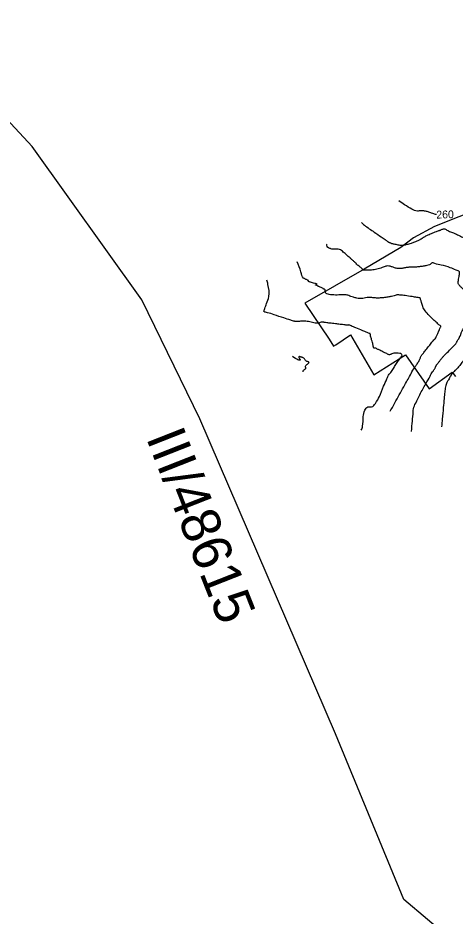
# Model space of a CAD drawing. Extents: x -478645 to -472650, y -1118147 to -1113892.
# Drawn here: x -476588 to -476364.6, y -1115811.7 to -1115352.3 of the extents above; entities that cross this region are included whole.
import ezdxf

# ---------------------------------------------------------------- set-up
doc = ezdxf.new("R2010")
doc.units = 0
for name, color, linetype in [('ObPÚ', 7, 'Continuous'), ('silnice', 7, 'Continuous'), ('Vrstevnice_hlavni', 7, 'Continuous'), ('Vrstevnice_popis', 7, 'Continuous'), ('Vrstevnice_vedlejsi', 7, 'Continuous')]:
    doc.layers.add(name, color=color, linetype=linetype)

msp = doc.modelspace()

# ---------------------------------------------------------------- linework, layer by layer
at = {"layer": 'ObPÚ'}
msp.add_lwpolyline([(-476350.14, -1115449), (-476375.02, -1115459.02), (-476385.85, -1115464.8), (-476392.23, -1115469.66), (-476411.03, -1115480.79), (-476441.42, -1115498.26), (-476428.9, -1115516.62), (-476426.71, -1115520.24), (-476425.46, -1115519.42), (-476418.11, -1115514.37), (-476406.06, -1115534.8), (-476390, -1115524.57), (-476377.76, -1115542), (-476366.06, -1115533.41), (-476364.38, -1115535.62)], dxfattribs=at)
at = {"layer": 'silnice'}
msp.add_lwpolyline([(-476162.8, -1116322.7), (-476200.543, -1116268.153), (-476239.965, -1116179.199), (-476260.934, -1116109.546), (-476288.613, -1116007.164), (-476289.451, -1115970.24), (-476274.354, -1115930.798), (-476261.922, -1115907.288), (-476366.595, -1115823.727), (-476390.845, -1115803.24), (-476425.665, -1115718.481), (-476494.983, -1115557.356), (-476524.795, -1115496.42), (-476580.823, -1115418.032), (-476641.911, -1115352.297)], dxfattribs=at)
at = {"layer": 'Vrstevnice_hlavni'}
for points in [[(-476374.118, -1115452.894), (-476374.632, -1115452.768), (-476375.379, -1115452.515), (-476376.616, -1115452.074), (-476378.342, -1115451.442), (-476380.123, -1115451.064), (-476381.96, -1115450.937), (-476383.851, -1115451.062), (-476386.654, -1115450.049), (-476390.368, -1115447.898), (-476393.306, -1115445.807)], [(-476442.249, -1115533.315), (-476442.258, -1115533.223), (-476442.035, -1115532.45), (-476441.322, -1115531.991), (-476440.926, -1115531.554), (-476440.848, -1115531.138), (-476441.086, -1115530.744), (-476441.04, -1115530.317), (-476440.708, -1115529.858), (-476440.091, -1115529.366), (-476439.638, -1115528.987), (-476439.349, -1115528.72), (-476439.224, -1115528.565), (-476439.347, -1115528.386), (-476439.718, -1115528.183), (-476440.335, -1115527.956), (-476440.852, -1115527.632), (-476441.268, -1115527.211), (-476441.584, -1115526.693), (-476441.969, -1115526.298), (-476442.426, -1115526.027), (-476442.953, -1115525.878), (-476443.443, -1115525.735), (-476443.895, -1115525.597), (-476444.309, -1115525.465), (-476444.44, -1115525.662), (-476444.286, -1115526.188), (-476443.849, -1115527.043), (-476447.74, -1115525.503)]]:
    msp.add_spline(points, degree=3, dxfattribs=at)
at = {"layer": 'Vrstevnice_vedlejsi'}
for points in [[(-476412.487, -1115456.977), (-476410.913, -1115458.262), (-476405.882, -1115461.815), (-476402.37, -1115464.29), (-476400.376, -1115465.685), (-476399.9, -1115466), (-476399.472, -1115466.293), (-476399.093, -1115466.564), (-476398.763, -1115466.813), (-476398.4, -1115467.035), (-476398.006, -1115467.232), (-476397.581, -1115467.402), (-476397, -1115467.583), (-476396.264, -1115467.775), (-476395.373, -1115467.977), (-476394.42, -1115468.176), (-476393.405, -1115468.369), (-476392.328, -1115468.558), (-476390.887, -1115468.463), (-476389.082, -1115468.084), (-476386.914, -1115467.422), (-476385.197, -1115466.84), (-476383.932, -1115466.337), (-476383.118, -1115465.915), (-476382.467, -1115465.566), (-476381.978, -1115465.291), (-476381.65, -1115465.088), (-476381.304, -1115464.864), (-476380.937, -1115464.618), (-476380.551, -1115464.349), (-476379.903, -1115463.998), (-476378.994, -1115463.563), (-476377.824, -1115463.044), (-476376.623, -1115462.523), (-476375.392, -1115462)], [(-476375.392, -1115462), (-476374.129, -1115461.473), (-476373.218, -1115461.118), (-476372.659, -1115460.933), (-476372.45, -1115460.919), (-476372.087, -1115460.802), (-476371.568, -1115460.58), (-476370.895, -1115460.255), (-476370.204, -1115460.181), (-476369.496, -1115460.36), (-476368.77, -1115460.791), (-476367.914, -1115461.219), (-476366.926, -1115461.642), (-476365.807, -1115462.062), (-476364.304, -1115462.716), (-476362.417, -1115463.605), (-476360.145, -1115464.728), (-476357.641, -1115465.438), (-476354.904, -1115465.734), (-476351.935, -1115465.618), (-476349.849, -1115465.502), (-476348.647, -1115465.387), (-476348.329, -1115465.272), (-476347.968, -1115465.34), (-476347.565, -1115465.59), (-476347.119, -1115466.023), (-476346.516, -1115466.573), (-476345.755, -1115467.242), (-476344.837, -1115468.03), (-476344.033, -1115469.141), (-476343.343, -1115470.576), (-476342.768, -1115472.335), (-476342.342, -1115473.633), (-476342.065, -1115474.468), (-476341.938, -1115474.841), (-476341.36, -1115475.721), (-476340.333, -1115477.106), (-476338.856, -1115478.997), (-476337.825, -1115480.446), (-476337.242, -1115481.454), (-476337.106, -1115482.02), (-476336.708, -1115482.699), (-476336.047, -1115483.489), (-476335.123, -1115484.392), (-476334.613, -1115485.234), (-476334.515, -1115486.014), (-476334.83, -1115486.732), (-476335.165, -1115487.505), (-476335.519, -1115488.332), (-476335.893, -1115489.212), (-476336.181, -1115489.954), (-476336.384, -1115490.556), (-476336.5, -1115491.018), (-476336.678, -1115491.638), (-476336.918, -1115492.417), (-476337.22, -1115493.354), (-476337.658, -1115494.21), (-476338.234, -1115494.984), (-476338.946, -1115495.678), (-476339.549, -1115496.226), (-476340.042, -1115496.627), (-476340.425, -1115496.883), (-476340.759, -1115497.34), (-476341.045, -1115497.997), (-476341.282, -1115498.856), (-476341.828, -1115499.854), (-476342.682, -1115500.993), (-476343.846, -1115502.272), (-476344.811, -1115503.411), (-476345.578, -1115504.411), (-476346.146, -1115505.272), (-476346.807, -1115506.216), (-476347.56, -1115507.242), (-476348.405, -1115508.352), (-476349.595, -1115510.321), (-476351.128, -1115513.152), (-476353.005, -1115516.842), (-476354.314, -1115519.344), (-476355.055, -1115520.656), (-476355.227, -1115520.78), (-476355.538, -1115521.104), (-476355.989, -1115521.629), (-476356.58, -1115522.354), (-476357.559, -1115523.662), (-476358.927, -1115525.554), (-476360.684, -1115528.028), (-476362.218, -1115530.038), (-476363.528, -1115531.584), (-476364.614, -1115532.666), (-476365.375, -1115533.438), (-476365.811, -1115533.898), (-476365.922, -1115534.047), (-476366.035, -1115534.195), (-476366.151, -1115534.34), (-476366.269, -1115534.483), (-476366.37, -1115534.607), (-476366.453, -1115534.711)], [(-476390.415, -1115480.123), (-476392.093, -1115480.442), (-476393.773, -1115480.449), (-476395.455, -1115480.141), (-476397.138, -1115479.52), (-476398.521, -1115479.202), (-476399.606, -1115479.187), (-476400.391, -1115479.474), (-476401.353, -1115479.819), (-476402.494, -1115480.221), (-476403.813, -1115480.681), (-476405.189, -1115481.004), (-476406.622, -1115481.191), (-476408.113, -1115481.24), (-476409.287, -1115481.28), (-476410.144, -1115481.31), (-476410.685, -1115481.331), (-476411.093, -1115481.319), (-476411.368, -1115481.273), (-476411.51, -1115481.194), (-476411.664, -1115481.065), (-476411.83, -1115480.886), (-476412.009, -1115480.658), (-476412.452, -1115480.262), (-476413.159, -1115479.699), (-476414.132, -1115478.968), (-476414.756, -1115478.466), (-476415.033, -1115478.195), (-476414.961, -1115478.152), (-476415.298, -1115477.773), (-476416.042, -1115477.057), (-476417.195, -1115476.004), (-476418.233, -1115475.067), (-476419.157, -1115474.246), (-476419.967, -1115473.541), (-476420.822, -1115472.803), (-476421.721, -1115472.032), (-476422.665, -1115471.228), (-476423.717, -1115470.72), (-476424.877, -1115470.508), (-476426.145, -1115470.593), (-476427.196, -1115470.561), (-476428.028, -1115470.413), (-476428.643, -1115470.148), (-476429.106, -1115469.938), (-476429.418, -1115469.785), (-476429.579, -1115469.688), (-476430.087, -1115468.492), (-476430.298, -1115467.927)], [(-476435.156, -1115488.388), (-476435.158, -1115488.388), (-476435.557, -1115488.278), (-476436.352, -1115488.058), (-476437.543, -1115487.729), (-476438.431, -1115487.476), (-476439.016, -1115487.299), (-476439.298, -1115487.198), (-476439.46, -1115487.083), (-476439.502, -1115486.954), (-476439.423, -1115486.81), (-476439.571, -1115486.628), (-476439.947, -1115486.406), (-476440.549, -1115486.147), (-476441.093, -1115485.887), (-476441.577, -1115485.629), (-476442.002, -1115485.371), (-476443.347, -1115482.202), (-476445.27, -1115477.051)], [(-476386.868, -1115563.77), (-476386.404, -1115558.49), (-476385.983, -1115553.73), (-476385.843, -1115552.17), (-476384.718, -1115549.256), (-476382.607, -1115544.988), (-476379.51, -1115539.367), (-476377.347, -1115535.488), (-476376.117, -1115533.352), (-476375.821, -1115532.959), (-476375.527, -1115532.539), (-476375.236, -1115532.091), (-476374.948, -1115531.616), (-476374.711, -1115531.173), (-476374.526, -1115530.763), (-476374.393, -1115530.385), (-476374.22, -1115530.026), (-476374.008, -1115529.686), (-476373.756, -1115529.365), (-476373.437, -1115528.968), (-476373.052, -1115528.496), (-476372.6, -1115527.948), (-476372.158, -1115527.393), (-476371.726, -1115526.831), (-476371.304, -1115526.261), (-476370.255, -1115525.116), (-476368.58, -1115523.398), (-476366.278, -1115521.105), (-476364.681, -1115519.417), (-476363.788, -1115518.333), (-476363.599, -1115517.854), (-476363.38, -1115517.403), (-476363.131, -1115516.981), (-476362.852, -1115516.586), (-476362.624, -1115516.208), (-476362.447, -1115515.848), (-476362.32, -1115515.506), (-476362.183, -1115515.228), (-476362.036, -1115515.015), (-476361.879, -1115514.866), (-476361.743, -1115514.589), (-476361.628, -1115514.182), (-476361.535, -1115513.647), (-476361.302, -1115513.008), (-476360.931, -1115512.265), (-476360.421, -1115511.418), (-476359.844, -1115510.674), (-476359.201, -1115510.032), (-476358.493, -1115509.493), (-476357.886, -1115508.861), (-476357.381, -1115508.138), (-476356.978, -1115507.323), (-476356.457, -1115506.284), (-476355.818, -1115505.02), (-476355.061, -1115503.532), (-476354.274, -1115502.169), (-476353.457, -1115500.932), (-476352.611, -1115499.821), (-476352.458, -1115498.76), (-476353, -1115497.749), (-476354.236, -1115496.789), (-476355.796, -1115495.443), (-476357.679, -1115493.713), (-476359.885, -1115491.598), (-476361.477, -1115490.015), (-476362.455, -1115488.962), (-476362.82, -1115488.441), (-476362.968, -1115487.633), (-476362.899, -1115486.539), (-476362.614, -1115485.158), (-476362.433, -1115483.976), (-476362.356, -1115482.993), (-476362.383, -1115482.21), (-476363.943, -1115481.232), (-476367.039, -1115480.058), (-476371.668, -1115478.69), (-476374.855, -1115477.913), (-476376.599, -1115477.729), (-476376.9, -1115478.137), (-476377.722, -1115478.533), (-476379.064, -1115478.919), (-476380.926, -1115479.294), (-476382.829, -1115479.558), (-476384.771, -1115479.713), (-476386.754, -1115479.758), (-476388.635, -1115479.895), (-476390.415, -1115480.123)], [(-476408.095, -1115513.705), (-476408.196, -1115513.728), (-476408.268, -1115513.743), (-476408.31, -1115513.748), (-476408.321, -1115513.745), (-476409.488, -1115513.249), (-476411.808, -1115512.262), (-476415.283, -1115510.782), (-476417.744, -1115509.807), (-476419.192, -1115509.336), (-476419.626, -1115509.37), (-476420.137, -1115509.365), (-476420.725, -1115509.322), (-476421.39, -1115509.24), (-476422.819, -1115509.072), (-476425.012, -1115508.818), (-476427.967, -1115508.478), (-476430.119, -1115508.208), (-476431.467, -1115508.009), (-476432.012, -1115507.881), (-476432.677, -1115507.898), (-476433.462, -1115508.059), (-476434.367, -1115508.365), (-476435.455, -1115508.435), (-476436.726, -1115508.27), (-476438.179, -1115507.87), (-476439.551, -1115507.597), (-476440.841, -1115507.45), (-476442.049, -1115507.43), (-476443.148, -1115507.446), (-476444.139, -1115507.499), (-476445.02, -1115507.589), (-476445.738, -1115507.612), (-476446.294, -1115507.568), (-476446.687, -1115507.457), (-476448.623, -1115506.848), (-476452.103, -1115505.741), (-476457.127, -1115504.136), (-476460.496, -1115503.043), (-476462.21, -1115502.463), (-476462.27, -1115502.394), (-476462.297, -1115502.311), (-476462.291, -1115502.212), (-476462.252, -1115502.098), (-476461.808, -1115500.826), (-476460.959, -1115498.396), (-476459.705, -1115494.808), (-476460.221, -1115488.599), (-476460.746, -1115486.336)], [(-476381.496, -1115524.576), (-476381.058, -1115524.018), (-476380.504, -1115523.329), (-476379.834, -1115522.508), (-476379.049, -1115521.557), (-476378.281, -1115520.592), (-476377.53, -1115519.614), (-476376.797, -1115518.624), (-476376.099, -1115517.755), (-476375.438, -1115517.009), (-476374.812, -1115516.386), (-476374.17, -1115515.401), (-476373.512, -1115514.054), (-476372.838, -1115512.345), (-476372.335, -1115511.13), (-476372.003, -1115510.408), (-476371.84, -1115510.178), (-476371.827, -1115509.979), (-476371.962, -1115509.811), (-476372.246, -1115509.672), (-476373.318, -1115508.746), (-476375.177, -1115507.032), (-476377.825, -1115504.531), (-476379.802, -1115502.156), (-476381.109, -1115499.909), (-476381.745, -1115497.789), (-476382.17, -1115496.348), (-476382.383, -1115495.585), (-476382.386, -1115495.5), (-476382.424, -1115495.445), (-476382.499, -1115495.418), (-476382.61, -1115495.421), (-476382.691, -1115495.424), (-476382.74, -1115495.427), (-476382.759, -1115495.431), (-476382.784, -1115495.429), (-476382.813, -1115495.421), (-476382.848, -1115495.408), (-476384.079, -1115495.216), (-476386.506, -1115494.845), (-476390.13, -1115494.294), (-476392.866, -1115494.036), (-476394.717, -1115494.071), (-476395.681, -1115494.399), (-476397.081, -1115494.728), (-476398.917, -1115495.058), (-476401.19, -1115495.39), (-476403.316, -1115495.546), (-476405.295, -1115495.527), (-476407.128, -1115495.333), (-476408.815, -1115495.309), (-476410.355, -1115495.455), (-476411.749, -1115495.772), (-476413.243, -1115495.824), (-476414.837, -1115495.61), (-476416.531, -1115495.132), (-476417.908, -1115494.707), (-476418.968, -1115494.337), (-476419.711, -1115494.02), (-476420.805, -1115493.856), (-476422.249, -1115493.843), (-476424.045, -1115493.982), (-476425.766, -1115494.011), (-476427.414, -1115493.928), (-476428.987, -1115493.735), (-476430.078, -1115493.424), (-476430.686, -1115492.995), (-476430.812, -1115492.449), (-476430.915, -1115491.994), (-476430.996, -1115491.631), (-476431.055, -1115491.359), (-476431.167, -1115491.175), (-476431.332, -1115491.079), (-476431.551, -1115491.071), (-476431.695, -1115491.04), (-476431.765, -1115490.986), (-476431.759, -1115490.908), (-476432.056, -1115490.718), (-476432.657, -1115490.416), (-476433.561, -1115490.002), (-476434.225, -1115489.683), (-476434.65, -1115489.461), (-476434.835, -1115489.334), (-476434.976, -1115489.24), (-476435.074, -1115489.18), (-476435.128, -1115489.153), (-476435.254, -1115489.108), (-476435.453, -1115489.045), (-476435.725, -1115488.965), (-476435.863, -1115488.891), (-476435.867, -1115488.824), (-476435.736, -1115488.763), (-476435.599, -1115488.688), (-476435.455, -1115488.598), (-476435.304, -1115488.493), (-476435.204, -1115488.423), (-476435.156, -1115488.388)], [(-476412.508, -1115563.171), (-476411.848, -1115561.069), (-476411.539, -1115556.209), (-476410.675, -1115552.946), (-476409.255, -1115551.281), (-476407.279, -1115551.213), (-476405.259, -1115549.425), (-476403.194, -1115545.916), (-476401.086, -1115540.688), (-476399.421, -1115536.885), (-476398.2, -1115534.51), (-476397.423, -1115533.561), (-476396.715, -1115532.584), (-476396.077, -1115531.58), (-476395.509, -1115530.549), (-476394.886, -1115529.538), (-476394.208, -1115528.545), (-476393.474, -1115527.573), (-476392.807, -1115526.632), (-476392.208, -1115525.724), (-476391.677, -1115524.848), (-476391.892, -1115524.233), (-476392.853, -1115523.879), (-476394.56, -1115523.785), (-476395.9, -1115523.836), (-476396.873, -1115524.031), (-476397.48, -1115524.372), (-476398.046, -1115524.521), (-476398.573, -1115524.479), (-476399.059, -1115524.246), (-476400.034, -1115523.767), (-476401.498, -1115523.043), (-476403.451, -1115522.073), (-476404.773, -1115521.441), (-476405.463, -1115521.147), (-476405.521, -1115521.191), (-476405.642, -1115521.2), (-476405.825, -1115521.174), (-476406.072, -1115521.112), (-476406.25, -1115520.912), (-476406.358, -1115520.574), (-476406.399, -1115520.096), (-476406.555, -1115519.343), (-476406.827, -1115518.313), (-476407.215, -1115517.007), (-476407.516, -1115515.936), (-476407.728, -1115515.1), (-476407.853, -1115514.499), (-476407.938, -1115514.074), (-476407.983, -1115513.826), (-476407.988, -1115513.754), (-476408.025, -1115513.714), (-476408.095, -1115513.705)], [(-476397.702, -1115553.445), (-476394.813, -1115548.217), (-476390.245, -1115539.924), (-476387.028, -1115534.168), (-476385.162, -1115530.949), (-476384.647, -1115530.266), (-476384.137, -1115529.535), (-476383.631, -1115528.757), (-476383.13, -1115527.931), (-476382.719, -1115527.161), (-476382.397, -1115526.448), (-476382.166, -1115525.791), (-476381.866, -1115525.167), (-476381.496, -1115524.576)], [(-476366.453, -1115534.711), (-476366.519, -1115534.795), (-476366.575, -1115534.884), (-476366.62, -1115534.978), (-476366.655, -1115535.077), (-476366.704, -1115535.185), (-476366.766, -1115535.301), (-476366.841, -1115535.425), (-476366.917, -1115535.543), (-476366.994, -1115535.653), (-476367.072, -1115535.756), (-476367.394, -1115536.315), (-476367.961, -1115537.331), (-476368.772, -1115538.804), (-476369.413, -1115540.903), (-476369.885, -1115543.629), (-476370.186, -1115546.981), (-476370.595, -1115551.582), (-476371.111, -1115557.431), (-476371.459, -1115561.384)]]:
    msp.add_spline(points, degree=3, dxfattribs=at)

# ---------------------------------------------------------------- texts
at = {"layer": 'silnice'}
msp.add_text('III/48615', height=20, rotation=291.50868, dxfattribs=at).set_placement((-476522.739, -1115566.913))
at = {"layer": 'Vrstevnice_popis'}
msp.add_text(' 260 ', height=4, rotation=1.48492, dxfattribs=at).set_placement((-476375.588, -1115454.953))

doc.saveas('drawing.dxf')
